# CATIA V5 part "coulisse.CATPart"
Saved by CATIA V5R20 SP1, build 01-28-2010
Part number: coulisse
Bounding box of the stored display mesh (mm): x -104.951 to -85.049, y 0 to 5, z -18.489 to 181.34
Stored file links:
  E:\EDELI\gcausse\Edeli_2012_190_gcausse\coulisse.CATPart
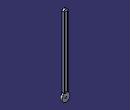
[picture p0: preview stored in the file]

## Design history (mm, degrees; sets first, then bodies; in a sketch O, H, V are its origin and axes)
Body1 (main body)
  Sketch1 on zx-plane, origin (0, 0, 0), H (-1, 0, 0), V (0, 0, 1)
    line L1 (90, 181.3397) -> (100, 181.3397)
    line L2 (100, 181.3397) -> (100, 0)
    line L3 (90, 0) -> (90, 181.3397)
    point P3 (100, 0)
    arc A1 centre (95, -8.6603) radius 10 from (90, 0) to (100, 0) ccw
    point P5 (95, -8.6603)
    line L4 (92.5, 176.3397) -> (97.5, 176.3397)
    line L5 (97.5, 176.3397) -> (97.5, 1.3397)
    line L6 (97.5, 1.3397) -> (92.5, 1.3397)
    line L7 (92.5, 1.3397) -> (92.5, 176.3397)
    circle A2 centre (95, -8.6603) radius 2.5
    radius A1 = 10
    distance L3 L2 = 10
    distance P5 L3 = 5
    distance L7 L5 = 5
    distance L1 P5 = 190
    distance L4 L1 = 5
    distance L7 L3 = 2.5
    distance L6 P5 = 10
    radius A2 = 2.5
    horizontal: L1 H, L4 H, L6 H
    vertical: L2 V, L3 V, L5 V, L7 V
    coincidence: P3 H
  Pad1: profile Sketch1, direction (0, 1, 0), length 5
  Fillet1: radius 5, on edge [face of Pad1 from Sketch1.L2 | face of Pad1 from Sketch1.A1]; edge [face of Pad1 from Sketch1.A1 | face of Pad1 from Sketch1.L3]; edge [face of Pad1 from Sketch1.L1 | face of Pad1 from Sketch1.L2]; edge [face of Pad1 from Sketch1.L3 | face of Pad1 from Sketch1.L1]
